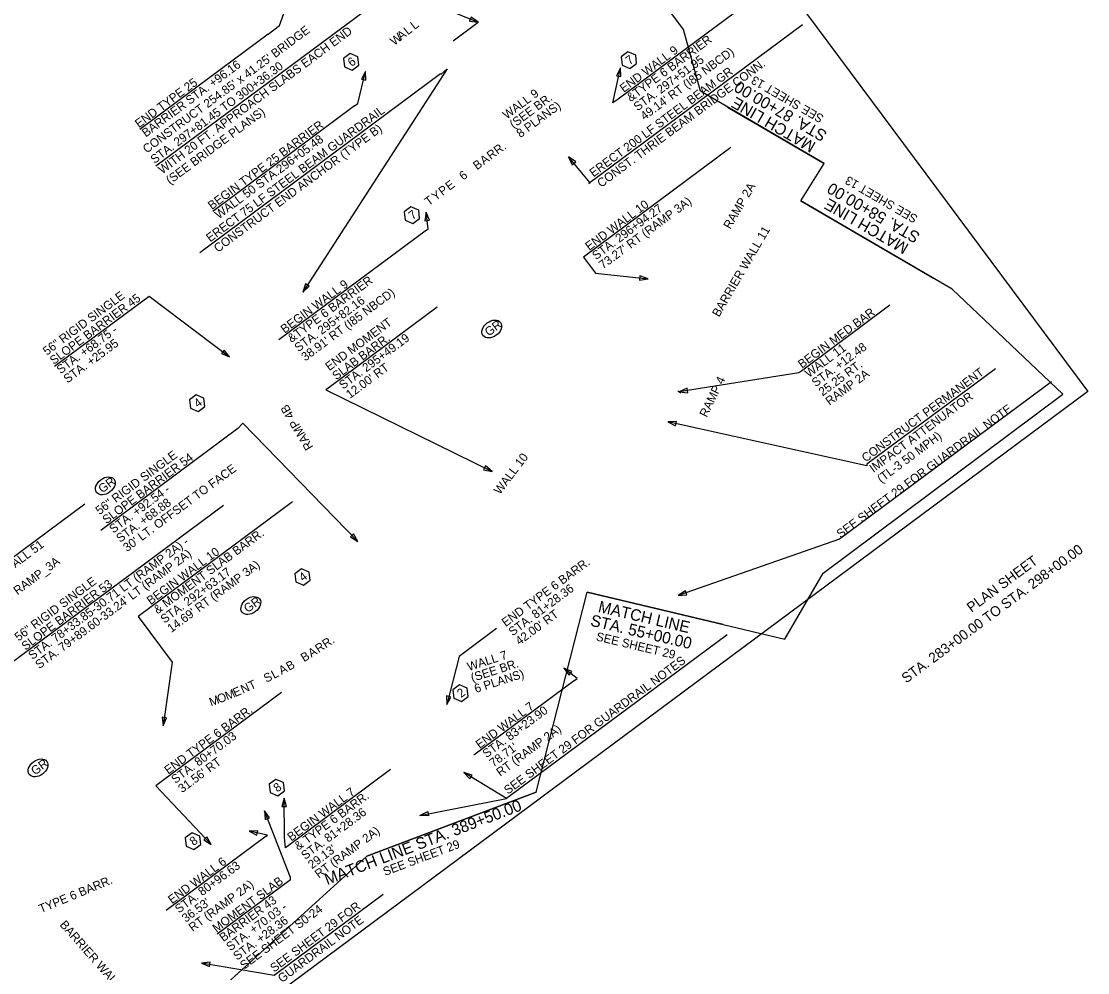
# Model space of a CAD drawing. Extents: x 1609621 to 1611756, y 1093008 to 1094970.
# Drawn here: x 1611016 to 1611756, y 1093621 to 1094282 of the extents above; entities that cross this region are included whole.
import ezdxf

# ---------------------------------------------------------------- set-up
doc = ezdxf.new("R2010")
doc.units = 0
for name, color, linetype in [('Level 2', 7, 'Continuous'), ('Plan_Clip', 7, 'Continuous'), ('RD_PD_GR_TX', 7, 'Continuous'), ('RD_SHT_MatchLine', 7, 'Continuous'), ('RD_SHT_Misc1', 7, 'Continuous'), ('RD_SHT_TX', 7, 'Continuous'), ('RD_TX_Bridge', 7, 'Continuous'), ('RD_TX_RoadID', 7, 'Continuous'), ('UC_AR_Telcom', 7, 'Continuous')]:
    doc.layers.add(name, color=color, linetype=linetype)

msp = doc.modelspace()

# ---------------------------------------------------------------- linework, layer by layer
at = {"layer": 'Level 2'}
msp.add_lwpolyline([(1609840.93, 1093792.96), (1611185.2, 1094792.24), (1611755.83, 1094024.6), (1610411.56, 1093025.32)], close=True, dxfattribs=at)
at = {"layer": 'Plan_Clip'}
msp.add_lwpolyline([(1610334.66, 1093203.95), (1610646.68, 1093232.42), (1610677.59, 1093225.95), (1610731.5, 1093266.37), (1610780.81, 1093327.58), (1610756.06, 1093348.11), (1610808.77, 1093414.81), (1610833.13, 1093414.54), (1610834.81, 1093427.58), (1610852.13, 1093534.14), (1611024.97, 1093492.08), (1611182.07, 1093635.05), (1611255.77, 1093702.11), (1611373.27, 1093746.55), (1611408.6, 1093885.46), (1611545.87, 1093852.79), (1611572.3, 1093898.6), (1611738.6, 1094022.91), (1611661.88, 1094095.64), (1611556.84, 1094157.06), (1611573.07, 1094182.91), (1611487.26, 1094233.09), (1611475.47, 1094276.05), (1611373.27, 1094413.52)], dxfattribs=at)
msp.add_lwpolyline([(1610334.66, 1093203.95), (1610646.68, 1093232.42), (1610677.59, 1093225.95), (1610731.5, 1093266.37), (1610780.81, 1093327.58), (1610756.06, 1093348.11), (1610808.77, 1093414.81), (1610833.13, 1093414.54), (1610834.81, 1093427.58), (1610852.13, 1093534.14), (1611024.97, 1093492.08), (1611182.07, 1093635.05), (1611255.77, 1093702.11), (1611373.27, 1093746.55), (1611408.6, 1093885.46), (1611545.87, 1093852.79), (1611572.3, 1093898.6), (1611738.6, 1094022.91), (1611661.88, 1094095.64), (1611556.84, 1094157.06), (1611573.07, 1094182.91), (1611487.26, 1094233.09), (1611475.47, 1094276.05), (1611373.27, 1094413.52)], dxfattribs=at)
at = {"layer": 'RD_PD_GR_TX'}
for p, q in [((1611558.06, 1094279.18), (1611409.9, 1094169.04)), ((1611306.94, 1094245.09), (1611139.99, 1094120.98)), ((1611691.95, 1094040.47), (1611602.74, 1093974.15)), ((1611471.46, 1094025.11), (1611473.62, 1094023.84)), ((1611505.73, 1093855.87), (1611354.6, 1093743.52)), ((1611292.5, 1093730.48), (1611352.74, 1093742.14)), ((1611267.11, 1093675.61), (1611192.41, 1093620.09))]:
    msp.add_line(p, q, dxfattribs=at)
for points in [[(1611307.13, 1094244.83), (1611311.6, 1094248.55), (1611211.37, 1094093.72)], [(1611409.9, 1094169.04), (1611410.66, 1094169.6), (1611395.78, 1094187.48)], [(1611730.74, 1094031.38), (1611583.76, 1093922.11), (1611471.81, 1093883.04)], [(1611602.74, 1093974.15), (1611602.53, 1093973.15), (1611464.52, 1094003.67)], [(1611354.6, 1093743.52), (1611352.74, 1093742.14), (1611323.19, 1093760.18)], [(1611192.41, 1093620.09), (1611191.5, 1093619.41), (1611141.19, 1093627.99)]]:
    msp.add_lwpolyline(points, dxfattribs=at)
for points in [[(1611400.68, 1094184.02), (1611395.78, 1094187.48), (1611398.3, 1094182.03)], [(1611213.22, 1094099.43), (1611211.37, 1094093.72), (1611215.82, 1094097.74)], [(1611470.52, 1094003.93), (1611464.52, 1094003.67), (1611469.85, 1094000.9)], [(1611476.77, 1093886.41), (1611471.81, 1093883.04), (1611477.79, 1093883.48)], [(1611328.94, 1093758.49), (1611323.19, 1093760.18), (1611327.32, 1093755.84)], [(1611298.68, 1093730.15), (1611292.5, 1093730.48), (1611298.11, 1093733.1)], [(1611147.17, 1093628.54), (1611141.19, 1093627.99), (1611146.64, 1093625.48)]]:
    msp.add_lwpolyline(points, close=True, dxfattribs=at)
at = {"layer": 'RD_SHT_MatchLine'}
for p, q in [((1611506.04, 1094222.11), (1611573.07, 1094182.91)), ((1611556.84, 1094157.06), (1611648.85, 1094103.26)), ((1611502.88, 1093863.02), (1611408.6, 1093885.46)), ((1611373.27, 1093746.55), (1611255.77, 1093702.11))]:
    msp.add_line(p, q, dxfattribs=at)
msp.add_lwpolyline([(1611475.47, 1094276.05), (1611410.77, 1094363.07), (1611373.27, 1094413.52)], dxfattribs=at)
at = {"layer": 'RD_SHT_TX'}
for p, q in [((1611532.39, 1094303.79), (1611430.06, 1094227.72)), ((1611315.77, 1094268.14), (1611333.03, 1094280.97)), ((1611187.42, 1094272.78), (1611098.31, 1094206.54)), ((1611247.35, 1094222.9), (1611148.91, 1094149.73)), ((1611508.4, 1094194.07), (1611406.07, 1094118)), ((1611297.14, 1094136.6), (1611194.81, 1094060.53)), ((1611304.64, 1094083.18), (1611230.55, 1094028.11)), ((1611618.65, 1094084.54), (1611558.2, 1094039.61)), ((1611166.38, 1093998.98), (1611071.23, 1093928.25)), ((1611060.15, 1093946.6), (1610971.27, 1093880.53)), ((1611156.42, 1093945.56), (1611008.22, 1093835.4)), ((1611204.24, 1093948.17), (1611097.13, 1093868.55)), ((1611399.77, 1093824.07), (1611330.08, 1093772.27)), ((1611196.57, 1093815.7), (1611114.15, 1093754.43)), ((1611272.31, 1093762.21), (1611199.44, 1093708.05)), ((1611186.01, 1093716.02), (1611116.71, 1093664.5)), ((1611202.94, 1093685.81), (1611152.08, 1093648.01))]:
    msp.add_line(p, q, dxfattribs=at)
for points in [[(1611187.42, 1094272.78), (1611195.33, 1094278.66), (1611203.18, 1094300.65)], [(1611247.35, 1094222.9), (1611249.66, 1094224.62), (1611254.84, 1094246.8)], [(1611430.06, 1094227.72), (1611426.5, 1094225.07), (1611431.66, 1094249.26)], [(1611297.14, 1094136.6), (1611298.45, 1094137.57), (1611296.96, 1094149.12)], [(1611406.07, 1094118), (1611414.4, 1094106.79), (1611450.86, 1094102.8)], [(1611039.25, 1094042.25), (1611104.79, 1094090.97), (1611160.53, 1094048.69)], [(1611558.2, 1094039.61), (1611555.47, 1094037.58), (1611472.54, 1094024.47)], [(1611230.55, 1094028.11), (1611227.36, 1094025.74), (1611342.65, 1093969.12)], [(1611166.38, 1093998.98), (1611169.85, 1094002.64), (1611249.57, 1093920.65)], [(1611097.13, 1093868.55), (1611120.76, 1093836.77), (1611114.5, 1093792.64)], [(1611345.75, 1093860.12), (1611319.75, 1093840.79), (1611311.22, 1093807.36)], [(1611399.77, 1093824.07), (1611401.71, 1093825.52), (1611392.53, 1093832.64)], [(1611114.15, 1093754.43), (1611109.37, 1093750.88), (1611147.76, 1093710.32)], [(1611199.44, 1093708.05), (1611198.8, 1093715.28), (1611198.39, 1093742.48)], [(1611202.94, 1093685.81), (1611202.83, 1093687.28), (1611184.73, 1093733.53)], [(1611186.01, 1093716.02), (1611186.98, 1093716.73), (1611174.11, 1093719.4)]]:
    msp.add_lwpolyline(points, dxfattribs=at)
for points in [[(1611249.67, 1094256.88), (1611244.34, 1094259.19), (1611239.68, 1094255.72), (1611240.35, 1094249.95), (1611245.68, 1094247.65), (1611250.34, 1094251.11)], [(1611442.3, 1094258.06), (1611436.97, 1094260.37), (1611432.3, 1094256.9), (1611432.98, 1094251.13), (1611438.31, 1094248.83), (1611442.97, 1094252.29)], [(1611255.03, 1094240.8), (1611254.84, 1094246.8), (1611252.01, 1094241.51)], [(1611431.97, 1094243.26), (1611431.66, 1094249.26), (1611428.94, 1094243.91)], [(1611291.78, 1094150.54), (1611286.45, 1094152.85), (1611281.79, 1094149.38), (1611282.46, 1094143.61), (1611287.79, 1094141.3), (1611292.45, 1094144.77)], [(1611299.24, 1094143.57), (1611296.96, 1094149.12), (1611296.16, 1094143.17)], [(1611444.93, 1094101.88), (1611450.86, 1094102.8), (1611445.27, 1094104.97)], [(1611154.98, 1094050.96), (1611160.53, 1094048.69), (1611156.85, 1094053.43)], [(1611142.85, 1094020.08), (1611137.52, 1094022.39), (1611132.86, 1094018.92), (1611133.53, 1094013.15), (1611138.86, 1094010.85), (1611143.52, 1094014.31)], [(1611478.02, 1094026.91), (1611472.54, 1094024.47), (1611478.5, 1094023.85)], [(1611336.76, 1093970.29), (1611342.65, 1093969.12), (1611338.13, 1093973.07)], [(1611244.42, 1093923.72), (1611249.57, 1093920.65), (1611246.64, 1093925.89)], [(1611215.8, 1093899.4), (1611210.46, 1093901.71), (1611205.8, 1093898.24), (1611206.47, 1093892.47), (1611211.8, 1093890.17), (1611216.47, 1093893.63)], [(1611398.06, 1093830.32), (1611392.53, 1093832.64), (1611396.16, 1093827.86)], [(1611325.43, 1093818.75), (1611320.09, 1093821.05), (1611315.43, 1093817.59), (1611316.1, 1093811.82), (1611321.43, 1093809.51), (1611326.1, 1093812.98)], [(1611311.15, 1093813.36), (1611311.22, 1093807.36), (1611314.16, 1093812.6)], [(1611113.78, 1093798.59), (1611114.5, 1093792.64), (1611116.85, 1093798.16)], [(1611198, 1093753.18), (1611192.67, 1093755.48), (1611188.01, 1093752.02), (1611188.68, 1093746.25), (1611194.01, 1093743.94), (1611198.67, 1093747.41)], [(1611200.03, 1093736.71), (1611198.39, 1093742.48), (1611196.92, 1093736.66)], [(1611188.29, 1093728.7), (1611184.73, 1093733.53), (1611185.4, 1093727.57)], [(1611180.1, 1093719.74), (1611174.11, 1093719.4), (1611179.47, 1093716.7)], [(1611139.89, 1093716.03), (1611134.55, 1093718.34), (1611129.89, 1093714.87), (1611130.56, 1093709.1), (1611135.89, 1093706.8), (1611140.56, 1093710.26)], [(1611142.65, 1093713.46), (1611147.76, 1093710.32), (1611144.9, 1093715.59)]]:
    msp.add_lwpolyline(points, close=True, dxfattribs=at)
at = {"layer": 'RD_TX_Bridge'}
msp.add_lwpolyline([(1611109.41, 1094181.36), (1611275.19, 1094304.59), (1611333.03, 1094280.97)], dxfattribs=at)
msp.add_lwpolyline([(1611327.08, 1094281.73), (1611333.03, 1094280.97), (1611328.25, 1094284.6)], close=True, dxfattribs=at)
at = {"layer": 'UC_AR_Telcom'}
for centre in [(1611342.48, 1094068.05), (1611074.44, 1093959.21), (1611175.35, 1093876.14), (1611027.75, 1093763.43)]:
    msp.add_ellipse(centre, major_axis=(6.09, 4.53), ratio=0.697574, dxfattribs=at)

# ---------------------------------------------------------------- texts
at = {"layer": 'RD_PD_GR_TX'}
for s, p in [('CONST. THRIE BEAM BRIDGE CONN.', (1611418.39, 1094166)), ('ERECT 200 LF STEEL BEAM GR', (1611413.02, 1094173.23)), ('ERECT 75 LF STEEL BEAM GUARDRAIL', (1611147.12, 1094128.15)), ('CONSTRUCT END ANCHOR (TYPE B)', (1611152.49, 1094120.92)), ('CONSTRUCT PERMANENT', (1611601.84, 1093975.35)), ('IMPACT ATTENUATOR', (1611607.21, 1093968.13)), ('SEE SHEET 29 FOR GUARDRAIL NOTE', (1611584.43, 1093922.61)), ('(TL-3 50 MPH)', (1611612.58, 1093960.91)), ('SEE SHEET 29 FOR GUARDRAIL NOTES', (1611353.71, 1093744.73)), ('SEE SHEET 29 FOR', (1611191.52, 1093621.29)), ('GUARDRAIL NOTE', (1611196.89, 1093614.07))]:
    msp.add_text(s, height=6, rotation=36.62722, dxfattribs=at).set_placement(p)
at = {"layer": 'RD_SHT_MatchLine'}
for s, height, rotation, p in [('STA. 87+00.00', 8, 149.86433, (1611575.73, 1094204.59)), ('SEE SHEET 13', 6, 149.9156, (1611573.34, 1094215.92)), ('MATCH LINE', 8, 149.86433, (1611567.85, 1094197.04)), ('SEE SHEET 13', 6, 149.9156, (1611638.52, 1094146.35)), ('STA. 58+00.00', 8, 149.86433, (1611640.22, 1094134.09)), ('MATCH LINE', 8, 149.86433, (1611632.34, 1094126.53)), ('MATCH LINE', 8, 346.77338, (1611415.76, 1093871.73)), ('STA. 55+00.00', 8, 346.77338, (1611410.41, 1093862.21)), ('SEE SHEET 29', 6, 346.60958, (1611414.4, 1093851.98)), ('MATCH LINE STA. 389+50.00', 8, 21.06531, (1611228.31, 1093681.99)), ('SEE SHEET 29', 6, 20.71665, (1611268.35, 1093688.34))]:
    msp.add_text(s, height=height, rotation=rotation, dxfattribs=at).set_placement(p)
at = {"layer": 'RD_SHT_Misc1'}
msp.add_text('SHEET 12-1', height=200, rotation=36.62559, dxfattribs=at).set_placement((1609913.35, 1093948.51))
at = {"layer": 'RD_SHT_TX'}
for s, rotation, p in [('W', 38.05769, (1611274.87, 1094264.54)), ('A', 38.05769, (1611279.56, 1094268.2)), ('L', 38.05769, (1611284.25, 1094271.87)), ('L', 38.05769, (1611288.93, 1094275.54)), ('&TYPE 6 BARRIER', 36.62559, (1611438.82, 1094225.51)), ('END WALL 9', 36.62559, (1611434.05, 1094231.93)), ("49.14' RT (I85 NBCD)", 36.62559, (1611448.37, 1094212.67)), ('BARRIER STA. +96.16', 36.62559, (1611102.53, 1094200.95)), ('6', 36.62559, (1611245.28, 1094249.88)), ('7', 36.62559, (1611438.02, 1094251.15)), ('STA. 297+51.95', 36.62559, (1611443.6, 1094219.09)), ('END TYPE 25 ', 36.62559, (1611097.75, 1094207.37)), ('WALL 9', 36.62559, (1611352.81, 1094213.41)), ('(SEE BR. ', 36.62559, (1611357.58, 1094206.99)), ('8 PLANS)', 36.62559, (1611362.35, 1094200.57)), ('BEGIN TYPE 25 BARRIER', 36.62559, (1611148.35, 1094150.56)), ('WALL 50 STA.296+05.48', 36.62559, (1611153.13, 1094144.14)), ('R', 36.62559, (1611341.81, 1094185.3)), ('R', 36.62559, (1611346.59, 1094188.85)), ('.', 36.62559, (1611351.36, 1094192.4)), ('B', 36.62559, (1611332.25, 1094178.19)), ('A', 36.62559, (1611337.03, 1094181.75)), ('6', 36.62559, (1611322.66, 1094171.06)), ('E', 36.62559, (1611313.07, 1094163.93)), ('Y', 36.62559, (1611303.51, 1094156.83)), ('P', 36.62559, (1611308.29, 1094160.38)), ('T', 36.62559, (1611298.74, 1094153.28)), ('END WALL 10', 36.62559, (1611410.06, 1094122.21)), ("73.27' RT (RAMP 3A)", 36.62559, (1611419.6, 1094109.37)), ('7', 36.62559, (1611287.51, 1094143.62)), ('STA. 296+94.27', 36.62559, (1611414.83, 1094115.79)), ('BARRIER WALL 11', 59.73206, (1611500.09, 1094075.93)), ('&TYPE 6 BARRIER', 36.62559, (1611203.58, 1094058.32)), ('BEGIN WALL 9', 36.62559, (1611198.8, 1094064.74)), ('56" RIGID SINGLE', 36.62559, (1611033.88, 1094049.47)), ('SLOPE BARRIER 45', 36.62559, (1611038.66, 1094043.05)), ('STA. 295+82.16', 36.62559, (1611208.35, 1094051.9)), ("38.91' RT (I85 NBCD)", 36.62559, (1611213.12, 1094045.48)), ('BEGIN MED.BAR', 36.62559, (1611557.65, 1094040.44)), ('END MOMENT ', 36.62559, (1611229.77, 1094038.75)), ('STA. +68.75 -', 36.62559, (1611043.43, 1094036.63)), ('GR', 36.62559, (1611340.36, 1094062.74)), ('STA. +25.95', 36.62559, (1611048.2, 1094030.21)), ('SLAB BARR.', 36.62559, (1611234.54, 1094032.33)), ('STA. 295+49.19', 36.62559, (1611239.31, 1094025.91)), ('WALL 11', 36.62559, (1611562.42, 1094034.02)), ('STA. +12.48', 36.62559, (1611567.19, 1094027.6)), ("12.00' RT ", 36.62559, (1611244.09, 1094019.49)), ('25.25 RT.', 36.62559, (1611571.97, 1094021.18)), ('RAMP 2A', 36.62559, (1611576.74, 1094014.76)), ('4', 36.62559, (1611138.58, 1094013.17)), ('56" RIGID SINGLE', 36.62559, (1611070.38, 1093938.84)), ('SLOPE BARRIER 54', 36.62559, (1611075.16, 1093932.42)), ('WALL 10', 52.84119, (1611348.17, 1093952.75)), ("30' LT. OFFSET TO FACE", 36.62559, (1611089.47, 1093913.16)), ('GR', 36.62559, (1611072.32, 1093953.9)), ('STA. +92.54 -', 36.62559, (1611079.93, 1093926)), ('STA. +68.88', 36.62559, (1611084.7, 1093919.58)), ('& MOMENT SLAB BARR.', 36.62559, (1611110.67, 1093869.89)), ('BARRIER WALL 51', 36.62559, (1610975.48, 1093874.94)), ('STA. 78+33.85-30.71 LT (RAMP 2A) -', 36.62559, (1611023.8, 1093838.25)), ("STA. 79+89.60-33.24' LT (RAMP 2A)", 36.62559, (1611028.57, 1093831.83)), ('BEGIN WALL 10', 36.62559, (1611105.9, 1093876.31)), ("77.35' LT RAMP_3A", 36.62559, (1610985.03, 1093862.1)), ("14.69' RT (RAMP 3A)", 36.62559, (1611120.22, 1093857.05)), ('END TYPE 6 BARR.', 36.62559, (1611352.13, 1093861.12)), ('STA. 292+63.17', 36.62559, (1611115.45, 1093863.47)), ('4', 36.62559, (1611211.52, 1093892.49)), ('56" RIGID SINGLE', 36.62559, (1611014.25, 1093851.09)), ('SLOPE BARRIER 53', 36.62559, (1611019.02, 1093844.67)), ('STA. 81+28.36', 36.62559, (1611356.9, 1093854.7)), ('GR', 36.62559, (1611173.23, 1093870.83)), ("42.00' RT", 36.62559, (1611361.67, 1093848.28)), ('R', 34.17491, (1611227.34, 1093846.3)), ('A', 32.34121, (1611217.33, 1093839.85)), ('R', 33.25806, (1611222.36, 1093843.03)), ('.', 35.09176, (1611232.26, 1093849.64)), ('WALL 7', 17.82519, (1611326.6, 1093830.62)), ('B', 29.58339, (1611201.9, 1093830.76)), ('B', 31.42436, (1611212.25, 1093836.75)), ('(SEE BR. ', 17.82519, (1611329.04, 1093823)), ('L', 27.74969, (1611191.41, 1093825.13)), ('A', 28.66654, (1611196.68, 1093827.91)), ('6 PLANS)', 17.82519, (1611331.49, 1093815.38)), ('T', 24.99187, (1611175.31, 1093817.31)), ('S', 26.83284, (1611186.1, 1093822.45)), ('O', 21.32447, (1611153.34, 1093808.12)), ('M', 22.24132, (1611158.89, 1093810.29)), ('E', 23.15817, (1611164.4, 1093812.54)), ('N', 24.07502, (1611169.87, 1093814.88)), ('2', 36.62559, (1611321.15, 1093811.83)), ('M', 20.40762, (1611147.76, 1093806.05)), ('END WALL 7', 36.62559, (1611334.07, 1093776.48)), ('END TYPE 6 BARR.', 36.62559, (1611118.13, 1093758.65)), ('STA. 83+23.90', 36.62559, (1611338.85, 1093770.06)), ('RT (RAMP 2A)', 36.62559, (1611348.39, 1093757.22)), ('STA. 80+70.03', 36.62559, (1611122.91, 1093752.22)), ("78.71' ", 36.62559, (1611343.62, 1093763.64)), ("31.56' RT", 36.62559, (1611127.68, 1093745.8)), ('GR', 36.62559, (1611025.63, 1093758.12)), ('8', 36.62559, (1611193.73, 1093746.26)), ('BEGIN WALL 7', 36.62559, (1611203.43, 1093712.26)), ('& TYPE 6 BARR.', 36.62559, (1611208.2, 1093705.84)), ('STA. 81+28.36', 36.62559, (1611212.98, 1093699.42)), ('RT (RAMP 2A)', 36.62559, (1611222.52, 1093686.58)), ('8', 36.62559, (1611135.61, 1093709.12)), ("29.13' ", 36.62559, (1611217.75, 1093693)), ('END WALL 6', 36.62559, (1611120.7, 1093668.71)), ('STA. 80+96.63', 36.62559, (1611125.47, 1093662.29)), ('TYPE 6 BARR.', 22.61628, (1611029.8, 1093662.52)), ('RT (RAMP 2A)', 36.62559, (1611135.01, 1093649.45)), ('MOMENT SLAB', 36.62559, (1611151.53, 1093648.84)), ("36.53' ", 36.62559, (1611130.24, 1093655.87)), ('BARRIER 43', 36.62559, (1611156.3, 1093642.42)), ('STA. +70.03 -', 36.62559, (1611161.07, 1093636)), ('SEE SHEET S0-24', 36.62559, (1611170.62, 1093623.16)), ('STA. +28.36', 36.62559, (1611165.85, 1093629.58)), ('BARRIER WALL 22', 311.41556, (1611042.41, 1093654.32))]:
    msp.add_text(s, height=6, rotation=rotation, dxfattribs=at).set_placement(p)
at = {"layer": 'RD_TX_Bridge'}
for s, p in [("CONSTRUCT 254.85' x 41.25' BRIDGE", (1611103.15, 1094189.79)), ('WITH 20 FT. APPROACH SLABS EACH END', (1611113.89, 1094175.34)), ('STA. 297+81.45 TO 300+36.30', (1611108.52, 1094182.56)), ('(SEE BRIDGE PLANS)', (1611119.26, 1094168.12))]:
    msp.add_text(s, height=6, rotation=36.62559, dxfattribs=at).set_placement(p)
at = {"layer": 'RD_TX_RoadID'}
for s, height, rotation, p in [('RAMP 2A', 6, 59.67509, (1611507.88, 1094136.94)), ('RAMP 4', 6, 64.08614, (1611491.62, 1094006.34)), ('RAMP 4B', 6, 121.0104, (1611218.8, 1093986.13)), ('STA. 283+00.00 TO STA. 298+00.00', 6.9833, 36.62559, (1611629.98, 1093821.9)), ('PLAN SHEET', 6.983, 36.62559, (1611675.25, 1093871.02))]:
    msp.add_text(s, height=height, rotation=rotation, dxfattribs=at).set_placement(p)

doc.saveas('drawing.dxf')
